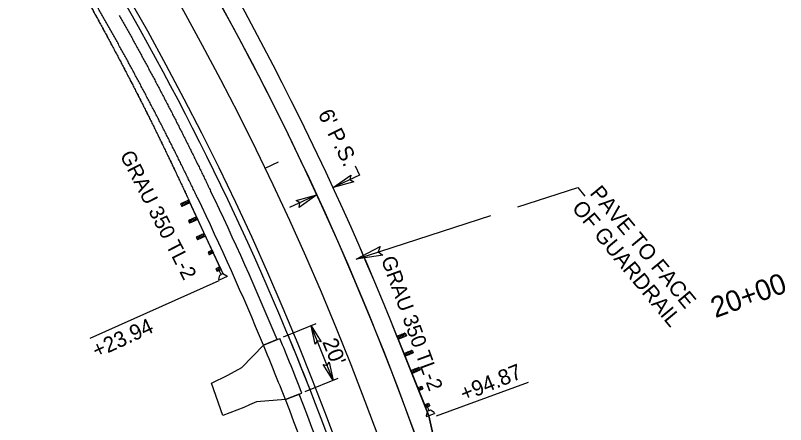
# Model space of a CAD drawing. Extents: x 2057680 to 2059216, y 687940 to 689338.
# Drawn here: x 2058908.2 to 2059168.9, y 688433.4 to 688571.9 of the extents above; entities that cross this region are included whole.
import ezdxf

# ---------------------------------------------------------------- set-up
doc = ezdxf.new("R2010")
doc.units = 0
for name, color, linetype in [('Cogo Default Point CELL', 7, 'Continuous'), ('Exist DTM Breakline Cogo Elevation', 7, 'Continuous'), ('Exist DTM Breakline Cogo Point CELL', 7, 'Continuous'), ('Exist DTM Regular Point Underwater Cogo Number', 7, 'Continuous'), ('Exist DTM Ridgeline Cogo Point CELL', 7, 'Continuous'), ('Exist Other Culture Located Object CELL', 7, 'Continuous'), ('Exist Roads EOP Cogo Elevation', 7, 'Continuous'), ('Exist Roads EOP Cogo Number', 7, 'Continuous'), ('Exist Roads Soil', 7, 'Continuous'), ('Exist Structure Major Bridge WW Cogo Point CELL', 7, 'Continuous'), ('Exist Structure Major Deck Tunnel Box Culvert Cogo Elevation', 7, 'Continuous'), ('Exist Structure Major Deck Tunnel Box Culvert Cogo Number', 7, 'Continuous'), ('Exist Structure Minor Pipes CMP 36 Inch Cogo Point CELL', 7, 'Continuous'), ('Exist Structure Minor Pipes HDPE 36 Inch', 7, 'Continuous'), ('Prop Conc 2ft 6in Curb and Gutter', 7, 'Continuous'), ('Prop Conc Drive Radius Type', 7, 'Continuous')]:
    doc.layers.add(name, color=color, linetype=linetype)

msp = doc.modelspace()

# ---------------------------------------------------------------- linework, layer by layer
at = {"layer": 'Cogo Default Point CELL'}
msp.add_arc((2058091.57, 688086.7), 1000, 13.85856, 62.50587, dxfattribs=at)
at = {"layer": 'Exist DTM Breakline Cogo Point CELL'}
for p, q in [((2058967.05, 688508.94), (2058977.62, 688486.29)), ((2059037.54, 688462.84), (2059046.86, 688439.64))]:
    msp.add_line(p, q, dxfattribs=at)
msp.add_arc((2058091.57, 688086.7), 1018.01, 21.68406, 33.8594, dxfattribs=at)
for points in [[(2058905.16, 688622.91), (2058905.63, 688622.17), (2058906.1, 688621.43), (2058906.57, 688620.68), (2058907.04, 688619.94), (2058907.5, 688619.2), (2058907.97, 688618.45), (2058908.43, 688617.71), (2058908.9, 688616.96), (2058909.36, 688616.22), (2058909.82, 688615.47), (2058910.29, 688614.72), (2058910.75, 688613.98), (2058911.21, 688613.23), (2058911.67, 688612.48), (2058912.13, 688611.74), (2058912.59, 688610.99), (2058913.05, 688610.24), (2058913.5, 688609.49), (2058913.96, 688608.74), (2058914.42, 688607.99), (2058914.87, 688607.24), (2058915.33, 688606.49), (2058915.78, 688605.74), (2058916.23, 688604.99), (2058916.69, 688604.24), (2058917.14, 688603.48), (2058917.59, 688602.73), (2058918.04, 688601.98), (2058918.49, 688601.22), (2058918.94, 688600.47), (2058919.39, 688599.72), (2058919.84, 688598.96), (2058920.28, 688598.21), (2058920.73, 688597.45), (2058921.18, 688596.7), (2058921.62, 688595.94), (2058922.07, 688595.18), (2058922.51, 688594.43), (2058922.95, 688593.67), (2058923.4, 688592.91), (2058923.84, 688592.15), (2058924.28, 688591.39), (2058924.72, 688590.64), (2058925.16, 688589.88), (2058925.6, 688589.12), (2058926.04, 688588.36), (2058926.47, 688587.6), (2058926.91, 688586.84), (2058927.35, 688586.07), (2058927.78, 688585.31), (2058928.22, 688584.55), (2058928.65, 688583.79), (2058929.09, 688583.03), (2058929.52, 688582.26), (2058929.95, 688581.5), (2058930.38, 688580.74), (2058930.81, 688579.97), (2058931.24, 688579.21), (2058931.67, 688578.44), (2058932.1, 688577.68), (2058932.53, 688576.91), (2058932.95, 688576.15), (2058933.38, 688575.38), (2058933.81, 688574.61), (2058934.23, 688573.84), (2058934.66, 688573.08), (2058935.08, 688572.31), (2058935.5, 688571.54), (2058935.93, 688570.77), (2058936.35, 688570), (2058936.77, 688569.23), (2058937.19, 688568.46), (2058937.61, 688567.69), (2058938.03, 688566.92)], [(2058938.03, 688566.92), (2058938.44, 688566.15), (2058938.86, 688565.38), (2058939.28, 688564.61), (2058939.69, 688563.84), (2058940.11, 688563.07), (2058940.52, 688562.29), (2058940.94, 688561.52), (2058941.35, 688560.75), (2058941.76, 688559.97), (2058942.18, 688559.2), (2058942.59, 688558.43), (2058943, 688557.65), (2058943.41, 688556.88), (2058943.82, 688556.1), (2058944.22, 688555.32), (2058944.63, 688554.55), (2058945.04, 688553.77), (2058945.44, 688552.99), (2058945.85, 688552.22), (2058946.26, 688551.44), (2058946.66, 688550.66), (2058947.06, 688549.88), (2058947.46, 688549.1), (2058947.87, 688548.33), (2058948.27, 688547.55), (2058948.67, 688546.77), (2058949.07, 688545.99), (2058949.47, 688545.21), (2058949.87, 688544.43), (2058950.26, 688543.64), (2058950.66, 688542.86), (2058951.06, 688542.08), (2058951.45, 688541.3), (2058951.85, 688540.52), (2058952.24, 688539.73), (2058952.63, 688538.95), (2058953.03, 688538.17), (2058953.42, 688537.38), (2058953.81, 688536.6), (2058954.2, 688535.81), (2058954.59, 688535.03), (2058954.98, 688534.24), (2058955.37, 688533.46), (2058955.76, 688532.67), (2058956.14, 688531.89), (2058956.53, 688531.1), (2058956.91, 688530.31), (2058957.3, 688529.53), (2058957.68, 688528.74), (2058958.07, 688527.95), (2058958.45, 688527.16), (2058958.83, 688526.37), (2058959.21, 688525.59), (2058959.59, 688524.8), (2058959.97, 688524.01), (2058960.35, 688523.22), (2058960.73, 688522.43), (2058961.11, 688521.64), (2058961.48, 688520.85), (2058961.86, 688520.05), (2058962.24, 688519.26), (2058962.61, 688518.47), (2058962.98, 688517.68), (2058963.36, 688516.89), (2058963.73, 688516.09), (2058964.1, 688515.3), (2058964.47, 688514.51), (2058964.84, 688513.71), (2058965.21, 688512.92), (2058965.58, 688512.12), (2058965.95, 688511.33), (2058966.32, 688510.54), (2058967.05, 688508.94)]]:
    msp.add_spline(points, degree=3, dxfattribs=at)
at = {"layer": 'Exist DTM Regular Point Underwater Cogo Number'}
msp.add_arc((2058091.57, 688086.7), 1018, 21.68406, 33.85941, dxfattribs=at)
for points in [[(2058905.17, 688622.92), (2058905.64, 688622.17), (2058906.11, 688621.43), (2058906.58, 688620.69), (2058907.04, 688619.94), (2058907.51, 688619.2), (2058907.98, 688618.46), (2058908.44, 688617.71), (2058908.91, 688616.97), (2058909.37, 688616.22), (2058909.83, 688615.48), (2058910.29, 688614.73), (2058910.76, 688613.98), (2058911.22, 688613.24), (2058911.68, 688612.49), (2058912.14, 688611.74), (2058912.6, 688610.99), (2058913.05, 688610.24), (2058913.51, 688609.49), (2058913.97, 688608.75), (2058914.42, 688608), (2058914.88, 688607.25), (2058915.33, 688606.49), (2058915.79, 688605.74), (2058916.24, 688604.99), (2058916.7, 688604.24), (2058917.15, 688603.49), (2058917.6, 688602.74), (2058918.05, 688601.98), (2058918.5, 688601.23), (2058918.95, 688600.48), (2058919.4, 688599.72), (2058919.85, 688598.97), (2058920.29, 688598.21), (2058920.74, 688597.46), (2058921.19, 688596.7), (2058921.63, 688595.94), (2058922.08, 688595.19), (2058922.52, 688594.43), (2058922.96, 688593.67), (2058923.4, 688592.92), (2058923.85, 688592.16), (2058924.29, 688591.4), (2058924.73, 688590.64), (2058925.17, 688589.88), (2058925.61, 688589.12), (2058926.04, 688588.36), (2058926.48, 688587.6), (2058926.92, 688586.84), (2058927.36, 688586.08), (2058927.79, 688585.32), (2058928.23, 688584.56), (2058928.66, 688583.79), (2058929.09, 688583.03), (2058929.53, 688582.27), (2058929.96, 688581.5), (2058930.39, 688580.74), (2058930.82, 688579.98), (2058931.25, 688579.21), (2058931.68, 688578.45), (2058932.11, 688577.68), (2058932.54, 688576.92), (2058932.96, 688576.15), (2058933.39, 688575.38), (2058933.82, 688574.62), (2058934.24, 688573.85), (2058934.67, 688573.08), (2058935.09, 688572.31), (2058935.51, 688571.55), (2058935.93, 688570.78), (2058936.36, 688570.01), (2058936.78, 688569.24), (2058937.2, 688568.47), (2058937.62, 688567.7), (2058938.04, 688566.93)], [(2058938.04, 688566.93), (2058938.45, 688566.16), (2058938.87, 688565.39), (2058939.29, 688564.62), (2058939.7, 688563.84), (2058940.12, 688563.07), (2058940.53, 688562.3), (2058940.95, 688561.53), (2058941.36, 688560.75), (2058941.77, 688559.98), (2058942.18, 688559.2), (2058942.6, 688558.43), (2058943.01, 688557.66), (2058943.42, 688556.88), (2058943.83, 688556.1), (2058944.23, 688555.33), (2058944.64, 688554.55), (2058945.05, 688553.78), (2058945.45, 688553), (2058945.86, 688552.22), (2058946.26, 688551.44), (2058946.67, 688550.67), (2058947.07, 688549.89), (2058947.47, 688549.11), (2058947.88, 688548.33), (2058948.28, 688547.55), (2058948.68, 688546.77), (2058949.08, 688545.99), (2058949.48, 688545.21), (2058949.87, 688544.43), (2058950.27, 688543.65), (2058950.67, 688542.87), (2058951.07, 688542.09), (2058951.46, 688541.3), (2058951.86, 688540.52), (2058952.25, 688539.74), (2058952.64, 688538.96), (2058953.04, 688538.17), (2058953.43, 688537.39), (2058953.82, 688536.6), (2058954.21, 688535.82), (2058954.6, 688535.03), (2058954.99, 688534.25), (2058955.38, 688533.46), (2058955.76, 688532.68), (2058956.15, 688531.89), (2058956.54, 688531.1), (2058956.92, 688530.32), (2058957.31, 688529.53), (2058957.69, 688528.74), (2058958.08, 688527.96), (2058958.46, 688527.17), (2058958.84, 688526.38), (2058959.22, 688525.59), (2058959.6, 688524.8), (2058959.98, 688524.01), (2058960.36, 688523.22), (2058960.74, 688522.43), (2058961.12, 688521.64), (2058961.49, 688520.85), (2058961.87, 688520.06), (2058962.24, 688519.27), (2058962.62, 688518.48), (2058962.99, 688517.68), (2058963.37, 688516.89), (2058963.74, 688516.1), (2058964.11, 688515.3), (2058964.48, 688514.51), (2058964.85, 688513.72), (2058965.22, 688512.92), (2058965.59, 688512.13), (2058965.96, 688511.33), (2058966.33, 688510.54), (2058967.06, 688508.95)]]:
    msp.add_spline(points, degree=3, dxfattribs=at)
at = {"layer": 'Exist DTM Ridgeline Cogo Point CELL'}
for p, q in [((2058966.85, 688509.4), (2058964.1, 688508.12)), ((2058965.9, 688507.85), (2058964.1, 688508.12)), ((2058964.1, 688508.12), (2058964.52, 688507.21)), ((2058964.52, 688507.21), (2058965.47, 688508.76)), ((2058967.27, 688508.5), (2058964.52, 688507.21)), ((2058965.47, 688508.76), (2058965.9, 688507.85)), ((2058965.47, 688508.76), (2058967.27, 688508.5)), ((2058966.85, 688509.4), (2058965.9, 688507.85)), ((2058966.85, 688509.4), (2058967.27, 688508.5)), ((2058977.63, 688486.29), (2058967.06, 688508.95)), ((2058969.49, 688503.74), (2058966.74, 688502.45)), ((2058968.54, 688502.19), (2058966.74, 688502.45)), ((2058966.74, 688502.45), (2058967.16, 688501.55)), ((2058967.16, 688501.55), (2058968.12, 688503.1)), ((2058969.91, 688502.83), (2058967.16, 688501.55)), ((2058968.12, 688503.1), (2058968.54, 688502.19)), ((2058968.12, 688503.1), (2058969.91, 688502.83)), ((2058969.49, 688503.74), (2058968.54, 688502.19)), ((2058969.49, 688503.74), (2058969.91, 688502.83)), ((2058972.13, 688498.07), (2058969.38, 688496.79)), ((2058969.81, 688495.88), (2058970.76, 688497.43)), ((2058972.56, 688497.17), (2058969.81, 688495.88)), ((2058970.76, 688497.43), (2058971.18, 688496.53)), ((2058970.76, 688497.43), (2058972.56, 688497.17)), ((2058972.13, 688498.07), (2058971.18, 688496.53)), ((2058972.13, 688498.07), (2058972.56, 688497.17)), ((2058971.18, 688496.53), (2058969.38, 688496.79)), ((2058969.38, 688496.79), (2058969.81, 688495.88)), ((2058974.78, 688492.41), (2058973.4, 688491.77)), ((2058974.78, 688492.41), (2058973.82, 688490.86)), ((2058974.78, 688492.41), (2058975.2, 688491.5)), ((2058973.4, 688491.77), (2058973.82, 688490.86)), ((2058973.4, 688491.77), (2058975.2, 688491.5)), ((2058975.2, 688491.5), (2058973.82, 688490.86)), ((2058977.42, 688486.75), (2058976.04, 688486.1)), ((2058977.42, 688486.75), (2058976.47, 688485.2)), ((2058977.42, 688486.75), (2058977.84, 688485.84)), ((2058976.04, 688486.1), (2058976.47, 688485.2)), ((2058976.04, 688486.1), (2058977.84, 688485.84)), ((2058977.84, 688485.84), (2058976.47, 688485.2)), ((2058977.8, 688484.2), (2058977.18, 688485.53)), ((2058977.34, 688483.98), (2058978.45, 688484.5)), ((2058977.83, 688485.84), (2058978.45, 688484.5)), ((2058978.45, 688484.5), (2058979.73, 688483.8)), ((2058977.06, 688482.56), (2058977.34, 688483.98)), ((2058977.06, 688482.56), (2058977.19, 688482.28)), ((2058979.86, 688483.52), (2058977.19, 688482.28)), ((2058979.73, 688483.8), (2058979.86, 688483.52)), ((2059037.34, 688463.3), (2059040.16, 688464.43)), ((2059037.34, 688463.3), (2059037.71, 688462.37)), ((2059037.34, 688463.3), (2059039.12, 688462.94)), ((2059038.75, 688463.87), (2059037.71, 688462.37)), ((2059037.71, 688462.37), (2059040.53, 688463.5)), ((2059038.75, 688463.87), (2059039.12, 688462.94)), ((2059040.53, 688463.5), (2059038.75, 688463.87)), ((2059039.12, 688462.94), (2059040.16, 688464.43)), ((2059040.16, 688464.43), (2059040.53, 688463.5)), ((2059046.85, 688439.64), (2059037.53, 688462.84)), ((2059039.67, 688457.5), (2059042.49, 688458.63)), ((2059041.08, 688458.07), (2059040.05, 688456.57)), ((2059041.08, 688458.07), (2059041.45, 688457.14)), ((2059042.86, 688457.71), (2059041.08, 688458.07)), ((2059041.45, 688457.14), (2059042.49, 688458.63)), ((2059042.49, 688458.63), (2059042.86, 688457.71)), ((2059039.67, 688457.5), (2059040.05, 688456.57)), ((2059039.67, 688457.5), (2059041.45, 688457.14)), ((2059040.05, 688456.57), (2059042.86, 688457.71)), ((2059042, 688451.7), (2059044.82, 688452.83)), ((2059043.78, 688451.34), (2059044.82, 688452.83)), ((2059044.82, 688452.83), (2059045.19, 688451.91)), ((2059042, 688451.7), (2059042.38, 688450.77)), ((2059042, 688451.7), (2059043.78, 688451.34)), ((2059043.41, 688452.27), (2059042.38, 688450.77)), ((2059042.38, 688450.77), (2059045.19, 688451.91)), ((2059043.41, 688452.27), (2059043.78, 688451.34)), ((2059045.19, 688451.91), (2059043.41, 688452.27)), ((2059044.33, 688445.9), (2059045.74, 688446.47)), ((2059044.33, 688445.9), (2059044.71, 688444.97)), ((2059044.33, 688445.9), (2059046.11, 688445.54)), ((2059045.74, 688446.47), (2059044.71, 688444.97)), ((2059044.71, 688444.97), (2059046.11, 688445.54)), ((2059045.74, 688446.47), (2059046.11, 688445.54)), ((2059046.66, 688440.1), (2059048.07, 688440.67)), ((2059046.66, 688440.1), (2059047.04, 688439.18)), ((2059046.66, 688440.1), (2059048.45, 688439.74)), ((2059048.07, 688440.67), (2059047.04, 688439.18)), ((2059047.04, 688439.18), (2059048.44, 688439.74)), ((2059048.07, 688440.67), (2059048.44, 688439.74)), ((2059047.05, 688439.18), (2059047.6, 688437.81)), ((2059047.6, 688437.81), (2059047.24, 688436.4)), ((2059047.35, 688436.12), (2059050.08, 688437.22)), ((2059048.73, 688438.27), (2059047.6, 688437.82)), ((2059048.26, 688438.08), (2059047.71, 688439.45)), ((2059049.97, 688437.5), (2059048.73, 688438.27)), ((2059049.97, 688437.5), (2059050.08, 688437.22)), ((2059047.24, 688436.4), (2059047.35, 688436.12))]:
    msp.add_line(p, q, dxfattribs=at)
at = {"layer": 'Exist Other Culture Located Object CELL'}
for p, q in [((2059023.2, 688521), (2059024.68, 688517.79)), ((2059024.68, 688517.79), (2059015.71, 688513.65)), ((2059078.23, 688507.06), (2059098.55, 688513.61)), ((2059098.55, 688513.61), (2059100.98, 688510.68)), ((2059010.26, 688511.13), (2059000.96, 688506.84)), ((2059023.52, 688489.41), (2059069.17, 688504.14)), ((2058933.49, 688462.66), (2058977.12, 688482.14)), ((2059009.85, 688467.51), (2058998.77, 688463.04)), ((2059015.78, 688448.34), (2059008.3, 688466.89)), ((2059017.33, 688448.97), (2059006.21, 688444.48)), ((2059081.77, 688447.68), (2059050.66, 688436.28))]:
    msp.add_line(p, q, dxfattribs=at)
at = {"layer": 'Exist Roads EOP Cogo Elevation'}
for p, q in [((2058996.76, 688462.22), (2058992.14, 688460.31)), ((2059004.23, 688443.69), (2058999.58, 688441.87))]:
    msp.add_line(p, q, dxfattribs=at)
for radius, start, end in [(975, 22.5315, 25.74805), (980, 22.5315, 25.74805), (980, 13.85856, 21.36309), (975, 13.85856, 21.36309)]:
    msp.add_arc((2058091.57, 688086.7), radius, start, end, dxfattribs=at)
for points in [[(2058938.82, 688569.7), (2058938.37, 688570.49), (2058937.92, 688571.28), (2058937.47, 688572.07), (2058937.03, 688572.86), (2058936.58, 688573.64), (2058936.13, 688574.43), (2058935.68, 688575.21), (2058935.23, 688576), (2058934.77, 688576.79), (2058934.32, 688577.57), (2058933.87, 688578.36), (2058933.41, 688579.14), (2058932.96, 688579.92), (2058932.5, 688580.71), (2058932.05, 688581.49), (2058931.59, 688582.27), (2058931.13, 688583.05), (2058930.67, 688583.83), (2058930.21, 688584.62), (2058929.75, 688585.4), (2058929.29, 688586.18), (2058928.83, 688586.96), (2058928.37, 688587.74), (2058927.91, 688588.51), (2058927.44, 688589.29), (2058926.98, 688590.07), (2058926.51, 688590.85), (2058926.05, 688591.63), (2058925.58, 688592.4), (2058925.11, 688593.18), (2058924.65, 688593.96), (2058924.18, 688594.73), (2058923.71, 688595.51), (2058923.24, 688596.28), (2058922.77, 688597.06), (2058922.3, 688597.83), (2058921.82, 688598.6), (2058921.35, 688599.38), (2058920.88, 688600.15), (2058920.4, 688600.92), (2058919.93, 688601.69), (2058919.45, 688602.46), (2058918.98, 688603.23), (2058918.5, 688604), (2058918.02, 688604.77), (2058917.54, 688605.54), (2058917.06, 688606.31), (2058916.58, 688607.08), (2058916.1, 688607.85), (2058915.62, 688608.62), (2058915.14, 688609.38), (2058914.65, 688610.15), (2058914.17, 688610.92), (2058913.69, 688611.68), (2058913.2, 688612.45), (2058912.72, 688613.21), (2058912.23, 688613.98), (2058911.74, 688614.74), (2058911.25, 688615.5), (2058910.76, 688616.27), (2058910.28, 688617.03), (2058909.78, 688617.79), (2058909.29, 688618.55), (2058908.8, 688619.32), (2058908.31, 688620.08), (2058907.82, 688620.84), (2058907.32, 688621.6), (2058906.83, 688622.36), (2058906.33, 688623.12), (2058905.84, 688623.87), (2058905.34, 688624.63), (2058904.84, 688625.39), (2058904.35, 688626.15), (2058903.85, 688626.9)], [(2058943.35, 688571.86), (2058943.79, 688571.07), (2058944.24, 688570.28), (2058944.68, 688569.49), (2058945.12, 688568.7), (2058945.57, 688567.91), (2058946.01, 688567.12), (2058946.45, 688566.32), (2058946.89, 688565.53), (2058947.33, 688564.74), (2058947.76, 688563.95), (2058948.2, 688563.16), (2058948.64, 688562.36), (2058949.07, 688561.57), (2058949.51, 688560.77), (2058949.94, 688559.98), (2058950.38, 688559.19), (2058950.81, 688558.39), (2058951.24, 688557.59), (2058951.67, 688556.8), (2058952.11, 688556), (2058952.54, 688555.2), (2058952.96, 688554.41), (2058953.39, 688553.61), (2058953.82, 688552.81), (2058954.25, 688552.01), (2058954.67, 688551.21), (2058955.1, 688550.42), (2058955.53, 688549.62), (2058955.95, 688548.82), (2058956.37, 688548.02), (2058956.8, 688547.21), (2058957.22, 688546.41), (2058957.64, 688545.61), (2058958.06, 688544.81), (2058958.48, 688544.01), (2058958.9, 688543.2), (2058959.32, 688542.4), (2058959.73, 688541.6), (2058960.15, 688540.79), (2058960.57, 688539.99), (2058960.98, 688539.19), (2058961.4, 688538.38), (2058961.81, 688537.58), (2058962.22, 688536.77), (2058962.64, 688535.96), (2058963.05, 688535.16), (2058963.46, 688534.35), (2058963.87, 688533.54), (2058964.28, 688532.73), (2058964.69, 688531.93), (2058965.09, 688531.12), (2058965.5, 688530.31), (2058965.91, 688529.5), (2058966.31, 688528.69), (2058966.72, 688527.88), (2058967.12, 688527.07), (2058967.52, 688526.26), (2058967.93, 688525.45), (2058968.33, 688524.64), (2058968.73, 688523.83), (2058969.13, 688523.01), (2058969.53, 688522.2), (2058969.93, 688521.39), (2058970.33, 688520.58), (2058970.72, 688519.76), (2058971.12, 688518.95), (2058971.52, 688518.13), (2058971.91, 688517.32), (2058972.31, 688516.5), (2058972.7, 688515.69), (2058973.09, 688514.87), (2058973.48, 688514.06), (2058974.27, 688512.42)], [(2058969.76, 688510.25), (2058968.98, 688511.89), (2058968.59, 688512.7), (2058968.19, 688513.52), (2058967.8, 688514.33), (2058967.41, 688515.15), (2058967.01, 688515.96), (2058966.61, 688516.78), (2058966.22, 688517.59), (2058965.82, 688518.41), (2058965.42, 688519.22), (2058965.02, 688520.03), (2058964.62, 688520.85), (2058964.22, 688521.66), (2058963.82, 688522.47), (2058963.42, 688523.28), (2058963.02, 688524.09), (2058962.61, 688524.91), (2058962.21, 688525.72), (2058961.8, 688526.53), (2058961.4, 688527.34), (2058960.99, 688528.15), (2058960.58, 688528.95), (2058960.17, 688529.76), (2058959.77, 688530.57), (2058959.36, 688531.38), (2058958.95, 688532.19), (2058958.53, 688532.99), (2058958.12, 688533.8), (2058957.71, 688534.61), (2058957.3, 688535.41), (2058956.88, 688536.22), (2058956.47, 688537.02), (2058956.05, 688537.83), (2058955.64, 688538.63), (2058955.22, 688539.44), (2058954.8, 688540.24), (2058954.38, 688541.04), (2058953.96, 688541.85), (2058953.54, 688542.65), (2058953.12, 688543.45), (2058952.7, 688544.25), (2058952.28, 688545.06), (2058951.85, 688545.86), (2058951.43, 688546.66), (2058951.01, 688547.46), (2058950.58, 688548.26), (2058950.15, 688549.06), (2058949.73, 688549.86), (2058949.3, 688550.65), (2058948.87, 688551.45), (2058948.44, 688552.25), (2058948.01, 688553.05), (2058947.58, 688553.85), (2058947.15, 688554.64), (2058946.72, 688555.44), (2058946.29, 688556.23), (2058945.85, 688557.03), (2058945.42, 688557.83), (2058944.98, 688558.62), (2058944.55, 688559.41), (2058944.11, 688560.21), (2058943.67, 688561), (2058943.24, 688561.79), (2058942.8, 688562.59), (2058942.36, 688563.38), (2058941.92, 688564.17), (2058941.48, 688564.96), (2058941.03, 688565.75), (2058940.59, 688566.54), (2058940.15, 688567.34), (2058939.71, 688568.12), (2058939.26, 688568.91), (2058938.82, 688569.7)]]:
    msp.add_spline(points, degree=3, dxfattribs=at)
at = {"layer": 'Exist Roads EOP Cogo Number'}
msp.add_line((2058992.74, 688520.16), (2058997.25, 688522.32), dxfattribs=at)
at = {"layer": 'Exist Structure Major Bridge WW Cogo Point CELL'}
for p, q in [((2059037.53, 688462.84), (2059048.14, 688436.43)), ((2059048.14, 688436.43), (2059052.51, 688416.6))]:
    msp.add_line(p, q, dxfattribs=at)
msp.add_arc((2058091.57, 688086.7), 1018, 21.68406, 33.85941, dxfattribs=at)
at = {"layer": 'Exist Structure Major Deck Tunnel Box Culvert Cogo Elevation'}
for p, q in [((2059048.14, 688436.43), (2059037.53, 688462.84)), ((2059052.51, 688416.6), (2059048.14, 688436.43))]:
    msp.add_line(p, q, dxfattribs=at)
for radius, start, end in [(1012, 13.85856, 37.17732), (1018, 21.68406, 33.85941)]:
    msp.add_arc((2058091.57, 688086.7), radius, start, end, dxfattribs=at)
at = {"layer": 'Exist Structure Major Deck Tunnel Box Culvert Cogo Number'}
for p, q in [((2058992.14, 688460.31), (2058984.87, 688452.7)), ((2058999.58, 688441.87), (2058989.77, 688441.14))]:
    msp.add_line(p, q, dxfattribs=at)
for points in [[(2058974.59, 688447.46), (2058980.14, 688450.14), (2058984.87, 688452.7)], [(2058989.77, 688441.14), (2058987.42, 688440.07), (2058985.51, 688439.21), (2058978.45, 688436.49), (2058974.59, 688447.46)]]:
    msp.add_lwpolyline(points, dxfattribs=at)
for radius in [1012, 986]:
    msp.add_arc((2058091.57, 688086.7), radius, 13.85856, 62.50587, dxfattribs=at)
at = {"layer": 'Exist Structure Minor Pipes CMP 36 Inch Cogo Point CELL'}
for p, q in [((2058992.14, 688460.31), (2058997.69, 688462.61)), ((2058999.58, 688441.87), (2059005.16, 688444.05))]:
    msp.add_line(p, q, dxfattribs=at)
for radius in [981, 975]:
    msp.add_arc((2058091.57, 688086.7), radius, 21.36309, 22.5315, dxfattribs=at)
at = {"layer": 'Exist Structure Minor Pipes HDPE 36 Inch'}
for points in [[(2059022.76, 688515.54), (2059015.71, 688513.65), (2059021.74, 688517.85), (2059021.44, 688516.3)], [(2059003.2, 688509.24), (2059010.26, 688511.13), (2059004.23, 688506.93), (2059004.52, 688508.48)], [(2059032.56, 688490.7), (2059023.52, 688489.41), (2059031.64, 688493.71), (2059031.04, 688491.84)], [(2059009.65, 688460.64), (2059008.3, 688466.89), (2059011.71, 688461.43), (2059010.37, 688461.76)], [(2059014.43, 688454.59), (2059015.78, 688448.34), (2059012.37, 688453.8), (2059013.71, 688453.47)]]:
    msp.add_lwpolyline(points, close=True, dxfattribs=at)
at = {"layer": 'Prop Conc 2ft 6in Curb and Gutter'}
msp.add_arc((2058091.57, 688086.7), 984, 13.85856, 33.91785, dxfattribs=at)
at = {"layer": 'Prop Conc Drive Radius Type'}
msp.add_arc((2058091.57, 688086.7), 984, 21.36319, 22.53147, dxfattribs=at)

# ---------------------------------------------------------------- texts
at = {"layer": 'Exist DTM Breakline Cogo Elevation'}
for s, rotation, p in [("6' P.S.", 296.5803, (2059010.46, 688538.52)), ('PAVE TO FACE', 309.6672, (2059102.4, 688511.59)), ('OF GUARDRAIL', 309.6672, (2059096.33, 688506.57)), ('+23.94', 24.7865, (2058935.69, 688455.78)), ("20'", 291.9292, (2059011.99, 688461.4)), ('+94.87', 22.0342, (2059060.05, 688441.18))]:
    msp.add_text(s, height=5.25, rotation=rotation, dxfattribs=at).set_placement(p)
at = {"layer": 'Exist DTM Ridgeline Cogo Point CELL'}
for rotation, p in [(297.0977, (2058943.43, 688524.58)), (290.0461, (2059031.89, 688489.4))]:
    msp.add_text('GRAU 350 TL-2', height=5, rotation=rotation, dxfattribs=at).set_placement(p)
at = {"layer": 'Exist Roads Soil'}
msp.add_text('20+00', height=7, rotation=19.9577, dxfattribs=at).set_placement((2059145.16, 688469.42))

doc.saveas('drawing.dxf')
